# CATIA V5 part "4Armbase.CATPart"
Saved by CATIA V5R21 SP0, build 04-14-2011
Part number: Armbase
Bounding box of the stored display mesh (mm): x -36 to 36, y -57.296 to 35, z 0 to 84.565
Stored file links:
  C:\Users\水心\Desktop\Arm_Detailed_Design_Assembly_Manu\4Armbase.CATPart
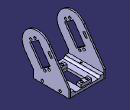
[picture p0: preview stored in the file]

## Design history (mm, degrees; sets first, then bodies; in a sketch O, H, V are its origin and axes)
Body1 (main body)
  Sketch1 on zx-plane, origin (0, 0, 0), H (-1, 0, 0), V (0, 0, 1)
    point P1 (-33, 0)
    line L1 (-33, 0) -> (-33, 9)
    point P2 (-33, 9)
    line L2 (-33, 9) -> (-26, 9)
    point P3 (-26, 9)
    line L3 (-26, 9) -> (-26, 5)
    point P4 (-26, 5)
    line L4 (-26, 5) -> (0, 5)
    point P5 (0, 5)
    line L5 (-33, 0) -> (0, 0)
    point P6 (0, 5)
    point P7 (26, 5)
    line L6 (26, 5) -> (0, 5)
    point P8 (26, 9)
    line L7 (26, 9) -> (26, 5)
    point P9 (33, 9)
    line L8 (33, 9) -> (26, 9)
    point P10 (33, 0)
    line L9 (33, 0) -> (33, 9)
    point P11 (0, 0)
    line L10 (33, 0) -> (0, 0)
    length L5 = 33
    distance L4 L5 = 5
    distance L2 L4 = 4
    length L2 = 7
    coincidence: P1 H, P5 V, O P11, P5 P6
    vertical: L1 V, L3 V
    horizontal: L2 H, L4 H, L5 H
    symmetry: P5 P6 V, P4 P7 V, L4 L6 V, P3 P8 V, L3 L7 V, P2 P9 V, L2 L8 V, P1 P10 V, L1 L9 V, O P11 V, L5 L10 V
  Pad1: profile Sketch1, direction (0, 1, 0), length 35, mirrored extent
  Fillet1: radius 4, on edge [face of Pad1 from Sketch1.L3 | face of Pad1 from Sketch1.L4]; edge [face of Pad1 from Sketch1.L6 | face of Pad1 from Sketch1.L7]
  Sketch2 on face of Pad1 from Sketch1.L6, origin (0, 0, 5), H (1, 0, 0), V (0, 1, 0)
    line L1 (-10.5, 25) -> (10.5, 25)
    line L2 (10.5, 25) -> (10.5, -15.5)
    line L3 (10.5, -15.5) -> (-10.5, -15.5)
    line L4 (-10.5, -15.5) -> (-10.5, 25)
    circle A1 centre (-5, 29) radius 2.5
    point P5 (-5, 29)
    circle A2 centre (5, 29) radius 2.5
    point P6 (5, 29)
    circle A3 centre (-5, -19.5) radius 2.5
    point P7 (-5, -19.5)
    circle A4 centre (5, -19.5) radius 2.5
    point P8 (5, -19.5)
    construction circle A5 centre (0, 15.34) radius 2.8695
    point P9 (0, 15.34)
    axis line L5 (-19.0638, 15.34) -> (25.8227, 15.34)
    length L2 = 40.5
    length L1 = 21
    distance L1 H = 25
    distance L2 V = 10.5
    radius A1 = 2.5
    radius A2 = 2.5
    radius A4 = 2.5
    distance P9 L1 = 9.66
    distance P6 L5 = 13.66
    distance P5 L5 = 13.66
    distance P5 P6 = 10
    distance P7 L5 = 34.84
    distance L5 P8 = 34.84
    distance P8 P7 = 10
    radius A3 = 2.5
    distance P5 V = 5
    distance V P7 = 5
    horizontal: L1 H, L3 H, L5 H
    vertical: L2 V, L4 V
    coincidence: P9 V, L5 P9
  Pocket1: profile Sketch2, direction (0, 0, -1), length 5
  Sketch3 on face of Pad1 from Sketch1.L9, origin (-33, 0, 0), H (0, -1, 0), V (0, 0, 1)
    circle A1 centre (-17.5, 4.5) radius 2.5
    point P1 (-17.5, 4.5)
    reference projected line E1 (35, 0) -> (-35, 0) from edge [face of Pad1 from Sketch1.L9 | face of Pad1 from Sketch1.L10]
    circle A2 centre (17.5, 4.5) radius 2.5
    radius A1 = 2.5
    distance P1 E1 = 4.5
    distance V P1 = 17.5
    symmetry: A1 A2 V
  Pocket2: profile Sketch3, direction (1, 0, 0), length 4
  Sketch4 on face of Pad1 from Sketch1.L1, origin (33, 0, 0), H (0, 1, 0), V (0, 0, 1)
    circle A1 centre (-17.5, 4.5) radius 2.5
    point P1 (-17.5, 4.5)
    reference projected line E1 (-35, 0) -> (35, 0) from edge [face of Pad1 from Sketch1.L5 | face of Pad1 from Sketch1.L1]
    circle A2 centre (17.5, 4.5) radius 2.5
    radius A1 = 2.5
    distance P1 V = 17.5
    distance P1 E1 = 4.5
    symmetry: A1 A2 V
  Pocket3: profile Sketch4, direction (-1, 0, 0), length 4
  Sketch5 on face of Pad1, origin (0, 0, 5), H (1, 0, 0), V (0, 1, 0)
    construction circle A1 centre (0, -5.84) radius 32
    point P1 (0, -5.84)
    reference projected line E1 (-26, -35) -> (26, -35) from edge [start face of Pad1 | face of Pad1]
    circle A2 centre (-29, -5.84) radius 1.5
    point P2 (-29, -5.84)
    circle A3 centre (29, -5.84) radius 1.5
    point P3 (29, -5.84)
    distance P1 E1 = 29.16
    radius A1 = 32
    radius A2 = 1.5
    distance P2 P1 = 29
    radius A3 = 1.5
    distance P1 P3 = 29
    coincidence: P1 V
  Pocket4: profile Sketch5, direction (0, 0, -1), length 6, mirrored extent
Body2
  Sketch6 on face of Pad1 from Sketch1.L9, origin (-33, 0, 0), H (0, -1, 0), V (0, 0, 1)
    point P1 (-35, 0)
    line L1 (-35, 0) -> (-35, 15)
    line L2 (-35, 15) -> (5.1504, 72.3406)
    arc A1 centre (28.6357, 55.896) radius 28.6703 from (5.1504, 72.3406) to (52.1211, 39.4514) cw
    line L3 (52.1211, 39.4514) -> (35, 15)
    line L4 (35, 15) -> (35, 0)
    point P7 (35, 0)
    line L5 (35, 0) -> (-35, 0)
    reference projected line E1 (35, 0) -> (35, 9) from edge [start face of Pad1 | face of Pad1 from Sketch1.L9]
    reference projected line E2 (-35, 0) -> (-35, 9) from edge [face of Pad1 from Sketch1.L9 | end face of Pad1]
    circle A2 centre (-17.5, 4.5) radius 2.5
    point P8 (-17.5, 4.5)
    circle A3 centre (17.5, 4.5) radius 2.5
    angle L2 L1 = 145
    length L1 = 15
    length L4 = 15
    length L2 = 70
    radius A2 = 2.5
    distance P8 L5 = 4.5
    distance P8 V = 17.5
    coincidence: P1 H, P7 H, L4 E1, L1 E2
    vertical: L1 V, L4 V
    tangency: A1 L2, L3 A1
    horizontal: L5 H
    parallelism: L3 L2
    symmetry: A2 A3 V
  Pad2: profile Sketch6, direction (-1, 0, 0), length 3
  Sketch7 on end face of Pad2, origin (-36, 0, 0), H (0, -1, 0), V (0, 0, 1)
    line L1 (25.5754, 69.8316) -> (42.7775, 57.7865)
    line L2 (42.7775, 57.7865) -> (19.5477, 24.6108)
    line L3 (19.5477, 24.6108) -> (2.3455, 36.6559)
    line L4 (2.3455, 36.6559) -> (25.5754, 69.8316)
    reference projected line E1 (1.258, 66.7818) -> (-33.1566, 17.6327) from edge [face of Pad2 from Sketch6.L2 | end face of Pad2]
    construction circle A1 centre (28.6357, 55.896) radius 3.7662
    point P5 (28.6357, 55.896)
    reference projected arc E2 centre (28.6357, 55.896) radius 28.6703 from (50.5984, 37.4671) to (6.673, 74.3249) ccw from edge [face of Pad2 from Sketch6.A1 | end face of Pad2]
    circle A2 centre (32.375, 69.9535) radius 2.5
    point P6 (32.375, 69.9535)
    circle A3 centre (40.5665, 64.2178) radius 2.5
    point P7 (40.5665, 64.2178)
    axis line L5 (44.6915, 44.6536) -> (17.7883, 63.4915)
    circle A4 centre (4.5565, 30.2246) radius 2.5
    point P10 (4.5565, 30.2246)
    circle A5 centre (12.7481, 24.4889) radius 2.5
    point P11 (12.7481, 24.4889)
    length L1 = 21
    length L2 = 40.5
    distance P5 L2 = 10.5
    distance P5 L1 = 9.66
    radius A2 = 2.5
    radius A3 = 2.5
    distance P6 L5 = 13.66
    distance P7 L5 = 13.66
    distance P6 P7 = 10
    distance P6 L4 = 5.5
    radius A4 = 2.5
    radius A5 = 2.5
    distance P10 P11 = 10
    length L5 = 32.8428
    distance P11 L5 = 34.84
    distance P10 L4 = 5.5
    distance L5 P10 = 34.84
    parallelism: L4 L2, L1 L3, L4 E1, L5 L1
    perpendicularity: L1 L2
    concentricity: A1 E2
    coincidence: L5 P5
  Pocket5: profile Sketch7, direction (1, 0, 0), length 5
  Sketch8 on face of Pad1 from Sketch1.L1, origin (33, 0, 0), H (0, 1, 0), V (0, 0, 1)
    projected line E1 (35, 0) -> (-35, 0) from edge [start face of Pad2 | face of Pad2 from Sketch6.L5]
    projected line E2 (-35, 0) -> (-35, 15) from edge [start face of Pad2 | face of Pad2 from Sketch6.L4]
    projected line E3 (-35, 15) -> (-52.1211, 39.4514) from edge [start face of Pad2 | face of Pad2 from Sketch6.L3]
    projected arc E4 centre (-28.6357, 55.896) radius 28.6703 from (-5.1504, 72.3406) to (-52.1211, 39.4514) ccw from edge [start face of Pad2 | face of Pad2 from Sketch6.A1]
    projected line E5 (-5.1504, 72.3406) -> (35, 15) from edge [start face of Pad2 | face of Pad2 from Sketch6.L2]
    projected line E6 (35, 15) -> (35, 0) from edge [start face of Pad2 | face of Pad2 from Sketch6.L1]
    projected line E7 (-25.5754, 69.8316) -> (-42.7775, 57.7865) from edge [start face of Pad2 | face of Pocket5 from Sketch7.L1]
    projected line E8 (-42.7775, 57.7865) -> (-19.5477, 24.6108) from edge [start face of Pad2 | face of Pocket5 from Sketch7.L2]
    projected line E9 (-19.5477, 24.6108) -> (-2.3455, 36.6559) from edge [start face of Pad2 | face of Pocket5 from Sketch7.L3]
    projected line E10 (-2.3455, 36.6559) -> (-25.5754, 69.8316) from edge [start face of Pad2 | face of Pocket5 from Sketch7.L4]
    projected circle E11 centre (-32.375, 69.9535) radius 2.5 from edge [face of Pocket5 from Sketch7.A2 | start face of Pad2]
    projected circle E12 centre (-40.5665, 64.2178) radius 2.5 from edge [face of Pocket5 from Sketch7.A3 | start face of Pad2]
    projected circle E13 centre (-4.5565, 30.2246) radius 2.5 from edge [face of Pocket5 from Sketch7.A4 | start face of Pad2]
    projected circle E14 centre (-12.7481, 24.4889) radius 2.5 from edge [face of Pocket5 from Sketch7.A5 | start face of Pad2]
    circle A1 centre (-17.5, 4.5) radius 2.5
    point P21 (-17.5, 4.5)
    circle A2 centre (17.5, 4.5) radius 2.5
    radius A1 = 2.5
    distance P21 E1 = 4.5
    distance P21 V = 17.5
    symmetry: A1 A2 V
  Pad3: profile Sketch8, direction (1, 0, 0), length 3
  Sketch9 on end face of Pad2, origin (-36, 0, 0), H (0, -1, 0), V (0, 0, 1)
    line L1 (3.5103, 61.2812) -> (-2.2254, 53.0897)
    line L2 (-2.2254, 53.0897) -> (1.0512, 50.7954)
    line L3 (1.0512, 50.7954) -> (6.787, 58.9869)
    line L4 (6.787, 58.9869) -> (3.5103, 61.2812)
    reference projected line E1 (5.1504, 72.3406) -> (-35, 15) from edge [face of Pad2 from Sketch6.L2 | end face of Pad2]
    reference projected line E2 (5.1504, 72.3406) -> (-35, 15) from edge [face of Pad2 from Sketch6.L2 | end face of Pad2]
    reference projected point E3 (-35, 15) from vertex [face of Pad2 from Sketch6.L1 | end face of Pad2 | face of Pad2 from Sketch6.L2]
    length L1 = 10
    length L4 = 4
    distance L1 E2 = 5
    distance L4 E3 = 60
    perpendicularity: L2 L1
    parallelism: L4 L2, L1 E1, L3 L1
  Pocket6: profile Sketch9, direction (1, 0, 0), through (limit type 3)
Body3
  Sketch10 on face of Pad1, origin (0, 0, 5), H (1, 0, 0), V (0, 1, 0)
    point P1 (-10.5, 33)
    line L1 (-10.5, 33) -> (10.5, 33)
    line L2 (10.5, 33) -> (10.5, 25)
    line L3 (10.5, 25) -> (-10.5, 25)
    line L4 (-10.5, 25) -> (-10.5, 33)
    point P2 (10.5, 33)
    point P3 (10.5, 25)
    point P4 (-10.5, 25)
    circle A1 centre (5, 29) radius 2.5
    circle A2 centre (-5, 29) radius 2.5
    reference projected circle E1 centre (5, 29) radius 2.5 from edge [face of Pad1 from Sketch1.L4 | face of Pocket1 from Sketch2.A2]
    reference projected circle E2 centre (-5, 29) radius 2.5 from edge [face of Pad1 from Sketch1.L6 | face of Pocket1 from Sketch2.A1]
    reference projected line E3 (10.5, 25) -> (-10.5, 25) from edge [face of Pad1 | face of Pocket1 from Sketch2.L1]
    axis line L5 (51.9835, 4.75) -> (-25.6214, 4.75)
    point P9 (-10.5, -23.5)
    point P10 (10.5, -23.5)
    point P11 (10.5, -15.5)
    point P12 (-10.5, -15.5)
    line L6 (-10.5, -23.5) -> (10.5, -23.5)
    line L7 (10.5, -23.5) -> (10.5, -15.5)
    line L8 (10.5, -15.5) -> (-10.5, -15.5)
    line L9 (-10.5, -15.5) -> (-10.5, -23.5)
    circle A3 centre (5, -19.5) radius 2.5
    circle A4 centre (-5, -19.5) radius 2.5
    length L2 = 8
    length L1 = 21
    distance V L2 = 10.5
    distance L5 L3 = 20.25
    horizontal: L1 H, L3 H, L5 H
    vertical: L2 V, L4 V
    coincidence: A1 E1, A2 E2, L3 E3
    symmetry: P1 P9 L5, P2 P10 L5, P3 P11 L5, P4 P12 L5, L1 L6 L5, L2 L7 L5, L3 L8 L5, L4 L9 L5, A1 A3 L5, A2 A4 L5
  Pad4: profile Sketch10, direction (0, 0, 1), length 6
